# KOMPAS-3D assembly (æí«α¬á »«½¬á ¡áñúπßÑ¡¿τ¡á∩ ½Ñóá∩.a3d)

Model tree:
1. Эскиз:1
     Ориентация = 2; Ориентация = 2

Referenced files in D:\АСКОН работа\Конкурс HOME\06_Сюваев_Сборная модель танка Т90\ДЕТАЛИ\КОРПУС\МЕТАЛЛ\КОРПУС ШТАМПОВКА\: надгусеничная полка левая.m3d, брызговик левый.m3d, глушитель.m3d
Referenced files in D:\АСКОН работа\Конкурс HOME\06_Сюваев_Сборная модель танка Т90\ДЕТАЛИ\КОРПУС\МЕТАЛЛ\КОРПУС ШТАМПОВКА\БАКИ\: Сборка бак левый 1.a3d, Сборка бак левый 2.a3d, Сборка бак левый 3.a3d, Сборка бак левый 5.a3d, бак левый 4.m3d
Referenced files in D:\АСКОН работа\Конкурс HOME\06_Сюваев_Сборная модель танка Т90\СБОРКИ\СБОРКА КОРПУСА ШТАМПОВКА\: Сборка экран левый.a3d
Referenced files in D:\АСКОН работа\Конкурс HOME\06_Сюваев_Сборная модель танка Т90\ДЕТАЛИ\ОБЩИЕ ДЕТАЛИ\: брызговик задний левый.m3d, поворот задн лев.m3d, ДЗ.m3d
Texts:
  Сборка полка надгусеничная левая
